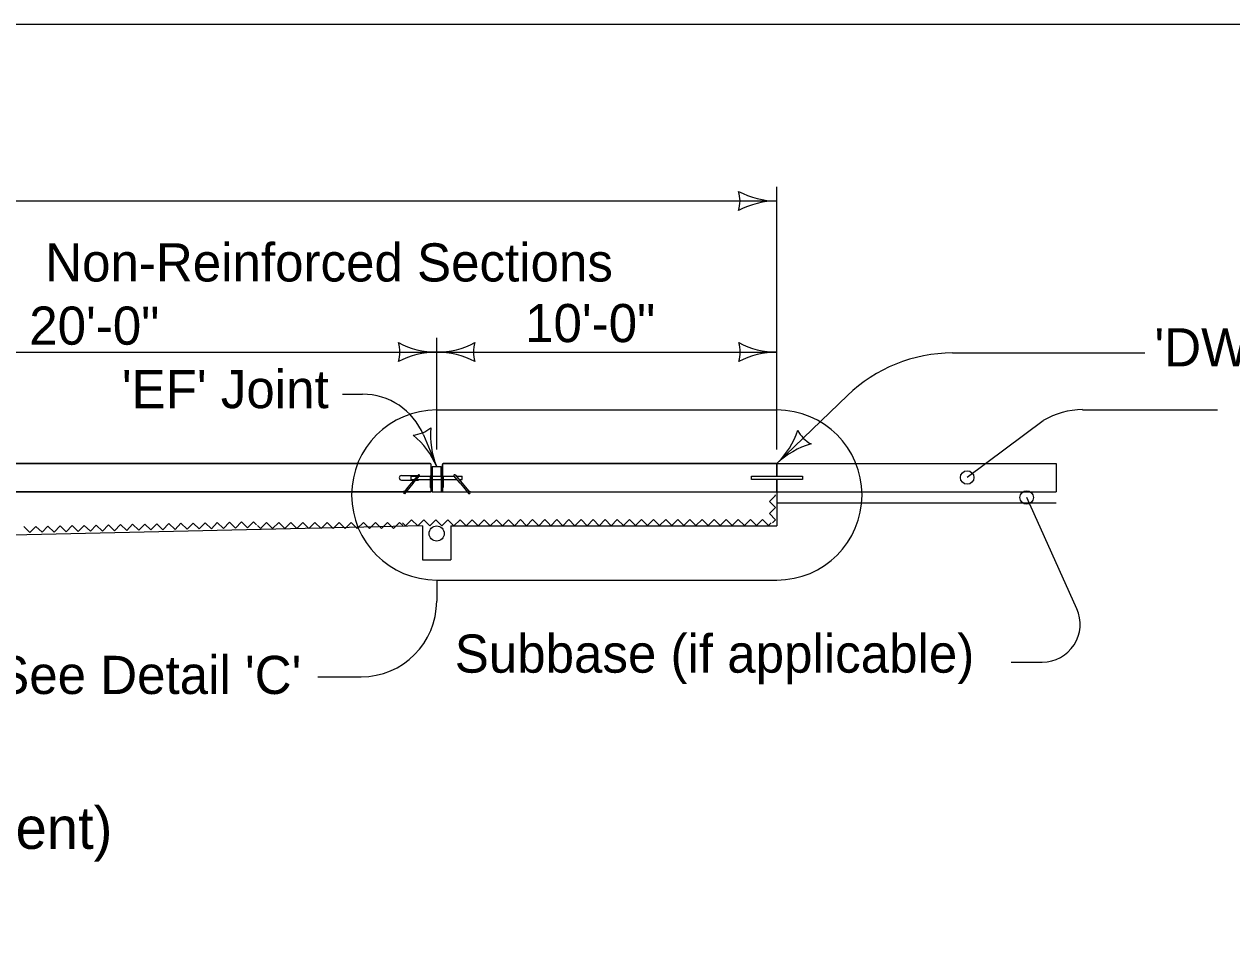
# Model space of a CAD drawing. Extents: x 10130 to 81668, y 5440 to 21644.
# Drawn here: x 15102 to 15735, y 7067 to 7554 of the extents above; entities that cross this region are included whole.
import ezdxf

# ---------------------------------------------------------------- set-up
doc = ezdxf.new("R2010")
doc.units = 0
for name, color, linetype in [('Cell', 7, 'Continuous'), ('dsnCellElements', 7, 'Continuous'), ('dsnStdBlockModified', 7, 'Continuous'), ('dsnStdBlockNotModified', 7, 'Continuous'), ('dsnStdBorder', 7, 'Continuous')]:
    doc.layers.add(name, color=color, linetype=linetype)

msp = doc.modelspace()

# ---------------------------------------------------------------- linework, layer by layer
at = {"layer": 'Cell'}
msp.add_lwpolyline([(13803.17, 7554.12), (16938.17, 7554.12), (16938.17, 5544.12), (13803.17, 5544.12)], close=True, dxfattribs=at)
at = {"layer": 'dsnCellElements'}
for centre in [(15596.22, 7316.59), (15627.37, 7306.09)]:
    msp.add_circle(centre, 3.54, dxfattribs=at)
at = {"layer": 'dsnStdBlockModified'}
for p, q in [((15496.58, 7331.28), (15496.58, 7468.91)), ((14157.11, 7461.48), (15496.58, 7461.48)), ((15318.38, 7331.28), (15318.38, 7389.71)), ((14961.98, 7382.28), (15318.38, 7382.28)), ((15318.38, 7382.28), (15496.58, 7382.28)), ((15588.54, 7381.82), (15689.23, 7381.82)), ((15269.11, 7360.25), (15279.46, 7360.25)), ((15496.58, 7323.85), (15533.47, 7359.54)), ((15318.38, 7351.95), (15496.58, 7351.95)), ((15656.65, 7352.11), (15727.26, 7352.11)), ((15636.08, 7346.35), (15596.22, 7316.59)), ((15653.61, 7247.79), (15627.37, 7306.09)), ((15318.38, 7262.85), (15318.38, 7251.75)), ((15318.38, 7262.85), (15496.58, 7262.85)), ((15619.33, 7219.86), (15635.56, 7219.86)), ((15256.14, 7212.15), (15278.78, 7212.15))]:
    msp.add_line(p, q, dxfattribs=at)
for centre, radius, start, end in [((15588.54, 7302.62), 79.2, 90, 134.04978), ((15279.46, 7325.6), 34.65, 22.59071, 90), ((15318.38, 7307.4), 44.55, 90, 270), ((15496.58, 7307.4), 44.55, 270, 90), ((15656.65, 7312.52), 39.6, 90, 121.29536), ((15278.78, 7251.75), 39.6, 270, 360), ((15635.56, 7239.67), 19.8, 270, 24.23803)]:
    msp.add_arc(centre, radius, start, end, dxfattribs=at)
at = {"layer": 'dsnStdBlockNotModified'}
for centre, radius, start, end in [((15282.75, 7382.28), 16.42, 342.26665, 17.73335), ((15318.38, 7424.78), 42.5, 241.92751, 270), ((15318.38, 7339.78), 42.5, 90, 118.07249), ((15318.38, 7424.78), 42.5, 270, 298.07249), ((15318.38, 7339.78), 42.5, 61.92751, 90), ((15354.02, 7382.28), 16.42, 162.26665, 197.73335), ((15460.95, 7382.28), 16.42, 342.26665, 17.73335), ((15496.58, 7424.78), 42.5, 241.92751, 270), ((15496.58, 7339.78), 42.5, 90, 118.07249), ((15304.69, 7355.15), 16.42, 274.86526, 310.33197), ((15279.15, 7305.92), 42.5, 22.59862, 50.6711), ((15357.62, 7338.58), 42.5, 174.52613, 202.59862), ((15467.03, 7354.4), 42.5, 314.0496, 342.12209), ((15522.2, 7348.63), 16.42, 206.31625, 241.78295), ((15526.13, 7293.31), 42.5, 105.97712, 134.0496)]:
    msp.add_arc(centre, radius, start, end, dxfattribs=at)
at = {"layer": 'dsnStdBorder'}
for p, q in [((15311.45, 7338.91), (15318.38, 7322.25)), ((14160.08, 7323.85), (15314.99, 7323.85)), ((15315, 7323.86), (14961.98, 7323.86)), ((15308.78, 7317.91), (15305.09, 7313.52)), ((15315.41, 7317.34), (15315.41, 7323.44)), ((15315.41, 7313.52), (15315.41, 7323.44)), ((15315.41, 7322.25), (15316.01, 7322.25)), ((15315.47, 7322.25), (15315.47, 7313.52)), ((15315.53, 7322.25), (15315.53, 7313.52)), ((15315.59, 7322.25), (15315.59, 7313.52)), ((15315.65, 7322.25), (15315.65, 7313.52)), ((15315.71, 7322.25), (15315.71, 7313.52)), ((15315.77, 7322.25), (15315.77, 7313.52)), ((15315.82, 7322.25), (15315.82, 7313.52)), ((15315.89, 7322.25), (15315.89, 7313.52)), ((15315.94, 7322.25), (15315.94, 7313.52)), ((15320.76, 7322.25), (15316.01, 7322.25)), ((15316.01, 7322.25), (15316.01, 7317.32)), ((15320.76, 7317.32), (15320.76, 7322.25)), ((15320.76, 7322.25), (15321.35, 7322.25)), ((15320.81, 7322.25), (15320.81, 7313.52)), ((15320.88, 7322.25), (15320.88, 7313.52)), ((15320.93, 7322.25), (15320.93, 7313.52)), ((15321, 7322.25), (15321, 7313.52)), ((15321.05, 7322.25), (15321.05, 7313.52)), ((15321.11, 7322.25), (15321.11, 7313.52)), ((15321.17, 7322.25), (15321.17, 7313.52)), ((15321.23, 7322.25), (15321.23, 7313.52)), ((15321.29, 7322.25), (15321.29, 7313.52)), ((15321.35, 7323.44), (15321.35, 7317.32)), ((15321.35, 7313.52), (15321.35, 7323.44)), ((15321.76, 7323.85), (15496.58, 7323.85)), ((15496.58, 7323.86), (15321.77, 7323.86)), ((15327.99, 7317.91), (15331.67, 7313.52)), ((15496.58, 7317.36), (15496.58, 7323.86)), ((15496.58, 7323.85), (15496.58, 7317.36)), ((15496.58, 7323.85), (15642.76, 7323.85)), ((15642.76, 7323.85), (15642.76, 7309)), ((15299.97, 7317.62), (15308.53, 7317.62)), ((15299.97, 7315.24), (15306.54, 7315.24)), ((15305.09, 7313.52), (15303.34, 7311.43)), ((15306.02, 7313.52), (15304.27, 7311.43)), ((15305.01, 7315.54), (15305.01, 7317.32)), ((15305.01, 7317.32), (15308.28, 7317.32)), ((15305.01, 7315.54), (15306.79, 7315.54)), ((15306.02, 7313.52), (15309.32, 7317.45)), ((15307.47, 7315.24), (15308.88, 7315.24)), ((15307.72, 7315.54), (15315.06, 7315.54)), ((15308.88, 7315.54), (15308.88, 7315.24)), ((15309.21, 7317.32), (15315.06, 7317.32)), ((15315.06, 7311.38), (15315.06, 7317.32)), ((15315.06, 7311.38), (15315.06, 7317.32)), ((15315.23, 7317.5), (15315.23, 7317.5)), ((15315.41, 7311.43), (15315.41, 7313.52)), ((15315.47, 7313.52), (15315.47, 7311.43)), ((15315.53, 7313.52), (15315.53, 7311.43)), ((15315.59, 7313.52), (15315.59, 7311.43)), ((15315.65, 7313.52), (15315.65, 7311.43)), ((15315.71, 7313.52), (15315.71, 7311.43)), ((15315.77, 7313.52), (15315.77, 7311.43)), ((15315.82, 7313.52), (15315.82, 7311.43)), ((15315.89, 7313.52), (15315.89, 7311.43)), ((15315.94, 7313.52), (15315.94, 7311.43)), ((15316.01, 7317.32), (15316.01, 7315.54)), ((15316.01, 7317.32), (15320.76, 7317.32)), ((15316.01, 7315.54), (15320.76, 7315.54)), ((15316.01, 7315.54), (15316.01, 7313.52)), ((15316.01, 7313.52), (15316.01, 7311.43)), ((15320.76, 7317.32), (15320.76, 7315.54)), ((15320.76, 7315.54), (15320.76, 7313.52)), ((15320.76, 7313.52), (15320.76, 7311.43)), ((15320.81, 7313.52), (15320.81, 7311.43)), ((15320.88, 7313.52), (15320.88, 7311.43)), ((15320.93, 7313.52), (15320.93, 7311.43)), ((15321, 7313.52), (15321, 7311.43)), ((15321.05, 7313.52), (15321.05, 7311.43)), ((15321.11, 7313.52), (15321.11, 7311.43)), ((15321.17, 7313.52), (15321.17, 7311.43)), ((15321.23, 7313.52), (15321.23, 7311.43)), ((15321.29, 7313.52), (15321.29, 7311.43)), ((15321.35, 7311.43), (15321.35, 7313.52)), ((15321.71, 7317.32), (15321.71, 7311.38)), ((15321.71, 7311.38), (15321.71, 7317.32)), ((15321.71, 7317.32), (15327.55, 7317.32)), ((15321.71, 7315.54), (15329.04, 7315.54)), ((15330.74, 7313.52), (15327.44, 7317.45)), ((15328.48, 7317.32), (15331.74, 7317.32)), ((15329.97, 7315.54), (15331.74, 7315.54)), ((15330.74, 7313.52), (15332.49, 7311.43)), ((15331.67, 7313.52), (15333.42, 7311.43)), ((15331.74, 7315.54), (15331.74, 7317.32)), ((15483.21, 7315.5), (15483.21, 7317.36)), ((15483.21, 7317.36), (15496.58, 7317.36)), ((15483.21, 7315.5), (15483.21, 7317.36)), ((15483.21, 7317.36), (15509.94, 7317.36)), ((15496.58, 7315.5), (15483.21, 7315.5)), ((15509.94, 7315.5), (15483.21, 7315.5)), ((15496.58, 7309.01), (15496.58, 7315.5)), ((15496.58, 7315.5), (15496.58, 7309)), ((15509.94, 7317.36), (15509.94, 7315.5)), ((15301.31, 7309), (14160.08, 7309)), ((14961.98, 7309.01), (15301.31, 7309.01)), ((15303.34, 7311.43), (15300.93, 7308.55)), ((15301.47, 7308.09), (15300.93, 7308.55)), ((15301.31, 7309.01), (15315.41, 7309.01)), ((15315.41, 7309), (15301.31, 7309.01)), ((15304.27, 7311.43), (15301.47, 7308.09)), ((15315.41, 7309), (15315.41, 7311.43)), ((15315.41, 7309.01), (15315.41, 7311.38)), ((15315.47, 7311.43), (15315.47, 7309)), ((15315.53, 7311.43), (15315.53, 7309)), ((15315.59, 7311.43), (15315.59, 7309)), ((15315.65, 7311.43), (15315.65, 7309)), ((15315.71, 7311.43), (15315.71, 7309)), ((15315.77, 7311.43), (15315.77, 7309)), ((15315.82, 7311.43), (15315.82, 7309)), ((15315.89, 7311.43), (15315.89, 7309)), ((15315.94, 7311.43), (15315.94, 7309)), ((15316.01, 7311.43), (15316.01, 7309)), ((15316.01, 7309), (15320.76, 7309)), ((15320.76, 7311.43), (15320.76, 7309)), ((15320.76, 7309), (15496.58, 7309)), ((15320.81, 7311.43), (15320.81, 7309)), ((15320.88, 7311.43), (15320.88, 7309)), ((15320.93, 7311.43), (15320.93, 7309)), ((15321, 7311.43), (15321, 7309)), ((15321.05, 7311.43), (15321.05, 7309)), ((15321.11, 7311.43), (15321.11, 7309)), ((15321.17, 7311.43), (15321.17, 7309)), ((15321.23, 7311.43), (15321.23, 7309)), ((15321.29, 7311.43), (15321.29, 7309)), ((15321.35, 7309), (15321.35, 7311.43)), ((15321.35, 7311.38), (15321.35, 7309.01)), ((15321.35, 7309.01), (15496.58, 7309.01)), ((15332.49, 7311.43), (15335.29, 7308.09)), ((15333.42, 7311.43), (15335.84, 7308.55)), ((15335.29, 7308.09), (15335.84, 7308.55)), ((15496.58, 7309), (15496.58, 7291.18)), ((15496.58, 7309), (15642.76, 7309)), ((15642.76, 7303.06), (15496.58, 7303.06)), ((15310.95, 7291.18), (14193.72, 7265.94)), ((15310.95, 7291.18), (15310.95, 7273.36)), ((15325.8, 7291.18), (15496.58, 7291.18)), ((15325.8, 7291.18), (15325.8, 7273.36)), ((15310.95, 7273.36), (15325.8, 7273.36))]:
    msp.add_line(p, q, dxfattribs=at)
for points in [[(15321.35, 7317.32), (15321.35, 7317.32)], [(15494.27, 7292.9), (15495.85, 7294.48), (15492.68, 7297.65), (15495.85, 7300.82), (15492.68, 7303.98), (15495.85, 7307.15), (15495.42, 7307.58)], [(15148.08, 7290.23), (15149.69, 7288.68), (15152.8, 7291.91), (15156.03, 7288.81), (15159.13, 7292.05), (15162.37, 7288.95), (15165.46, 7292.18), (15168.7, 7289.09), (15171.8, 7292.32), (15175.03, 7289.22), (15178.13, 7292.46), (15181.37, 7289.35), (15184.47, 7292.59), (15187.7, 7289.49), (15190.8, 7292.73), (15194.04, 7289.62), (15197.14, 7292.86), (15200.37, 7289.76), (15203.47, 7293), (15206.71, 7289.9), (15209.81, 7293.13), (15213.04, 7290.03), (15216.14, 7293.27), (15219.37, 7290.17), (15222.48, 7293.4), (15224.09, 7291.85)], [(15224.55, 7291.39), (15226.13, 7289.81), (15229.3, 7292.97), (15232.47, 7289.81), (15235.63, 7292.99), (15238.81, 7289.82), (15241.97, 7292.99), (15245.14, 7289.83), (15248.31, 7293), (15251.48, 7289.84), (15254.64, 7293.01), (15257.81, 7289.85), (15260.98, 7293.02), (15264.15, 7289.85), (15267.31, 7293.03), (15270.49, 7289.86), (15273.65, 7293.03), (15276.82, 7289.87), (15279.99, 7293.04), (15283.16, 7289.88), (15286.32, 7293.05), (15289.49, 7289.89), (15292.66, 7293.06), (15295.83, 7289.89), (15298.99, 7293.07), (15300.58, 7291.49)], [(15300.52, 7292.88), (15302.11, 7291.3), (15305.27, 7294.46), (15308.44, 7291.3), (15311.61, 7294.46), (15314.78, 7291.3), (15317.95, 7294.47), (15321.11, 7291.3), (15324.28, 7294.47), (15327.45, 7291.3), (15330.62, 7294.47), (15333.79, 7291.3), (15336.95, 7294.48), (15340.12, 7291.31), (15343.29, 7294.48), (15346.46, 7291.31), (15349.63, 7294.48), (15352.79, 7291.31), (15355.96, 7294.48), (15359.13, 7291.32), (15362.3, 7294.49), (15365.47, 7291.32), (15368.63, 7294.49), (15371.8, 7291.32), (15374.97, 7294.49), (15376.55, 7292.91)], [(15376.55, 7292.91), (15378.14, 7291.32), (15381.31, 7294.5), (15384.47, 7291.33), (15387.64, 7294.5), (15390.81, 7291.33), (15393.98, 7294.5), (15397.15, 7291.33), (15400.31, 7294.5), (15403.48, 7291.33), (15406.65, 7294.5), (15409.82, 7291.33), (15412.99, 7294.5), (15416.15, 7291.34), (15419.32, 7294.51), (15422.49, 7291.34), (15425.66, 7294.51), (15428.83, 7291.34), (15431.99, 7294.51), (15435.16, 7291.34), (15438.33, 7294.52), (15441.5, 7291.35), (15444.67, 7294.52), (15447.83, 7291.35), (15451, 7294.52), (15452.59, 7292.93)], [(15452.59, 7292.93), (15454.17, 7291.35), (15457.34, 7294.52), (15460.51, 7291.35), (15463.67, 7294.53), (15466.84, 7291.36), (15470.01, 7294.53), (15473.18, 7291.36), (15476.35, 7294.53), (15479.51, 7291.36), (15482.68, 7294.53), (15485.85, 7291.37), (15489.02, 7294.53), (15492.19, 7291.37), (15493.56, 7292.74)], [(15102.12, 7290.83), (15105.35, 7287.73), (15108.46, 7290.96), (15111.69, 7287.87), (15114.79, 7291.1), (15118.02, 7288), (15121.12, 7291.24), (15124.36, 7288.14), (15127.46, 7291.37), (15130.69, 7288.27), (15133.79, 7291.51), (15137.03, 7288.4), (15140.13, 7291.64), (15143.36, 7288.54), (15146.46, 7291.78), (15148.08, 7290.23)]]:
    msp.add_lwpolyline(points, dxfattribs=at)
for centre, radius in [((15306.03, 7315), 0.238), ((15330.49, 7315.3), 0.238), ((15301.2, 7309.24), 0.238), ((15335.57, 7309.24), 0.238), ((15318.38, 7287.22), 3.96)]:
    msp.add_circle(centre, radius, dxfattribs=at)
for centre, radius, start, end in [((15460.74, 7461.48), 16.51, 342.26665, 17.73335), ((15496.58, 7504.23), 42.75, 241.92751, 270), ((15460.74, 7461.48), 16.51, 342.26665, 17.73335), ((15496.58, 7504.23), 42.75, 241.92751, 270), ((15496.58, 7418.73), 42.75, 90, 118.07249), ((15496.58, 7418.73), 42.75, 90, 118.07249), ((15309.05, 7317.68), 0.356, 320.00367, 139.99636), ((15315, 7323.44), 0.416, 360, 90), ((15315, 7323.44), 0.416, 0, 90), ((15321.77, 7323.44), 0.416, 90, 180), ((15321.77, 7323.44), 0.416, 90, 180), ((15327.72, 7317.68), 0.356, 40.00364, 219.99633), ((15299.97, 7316.43), 1.19, 90, 270), ((15315.23, 7317.32), 0.178, 5.43269, 180), ((15315.24, 7317.32), 0.178, 0, 180), ((15315.24, 7317.32), 0.178, 0, 180), ((15321.53, 7317.32), 0.178, 0, 180), ((15321.53, 7317.32), 0.178, 0, 180), ((15315.23, 7311.38), 0.178, 180, 359.93724), ((15315.24, 7311.38), 0.178, 180, 0), ((15321.53, 7311.38), 0.178, 180, 0), ((15321.53, 7311.38), 0.178, 180, 0)]:
    msp.add_arc(centre, radius, start, end, dxfattribs=at)
for points in [[(15321.71, 7317.2), (15321.74, 7317.2), (15321.77, 7317.2), (15321.8, 7317.2), (15321.82, 7317.2), (15321.84, 7317.2), (15321.85, 7317.2)], [(15321.71, 7317.08), (15321.74, 7317.08), (15321.77, 7317.08), (15321.8, 7317.08), (15321.82, 7317.08), (15321.84, 7317.08), (15321.85, 7317.08)], [(15321.71, 7316.96), (15321.74, 7316.96), (15321.77, 7316.96), (15321.8, 7316.96), (15321.82, 7316.96), (15321.84, 7316.96), (15321.85, 7316.96)], [(15321.71, 7316.85), (15321.74, 7316.84), (15321.77, 7316.85), (15321.8, 7316.85), (15321.82, 7316.85), (15321.84, 7316.84), (15321.85, 7316.85)], [(15321.71, 7316.73), (15321.74, 7316.72), (15321.77, 7316.73), (15321.8, 7316.73), (15321.82, 7316.73), (15321.84, 7316.72), (15321.85, 7316.73)], [(15321.71, 7316.61), (15321.74, 7316.6), (15321.77, 7316.61), (15321.8, 7316.61), (15321.82, 7316.61), (15321.84, 7316.6), (15321.85, 7316.61)], [(15321.71, 7316.49), (15321.74, 7316.48), (15321.77, 7316.49), (15321.8, 7316.49), (15321.82, 7316.49), (15321.84, 7316.48), (15321.85, 7316.49)], [(15321.71, 7316.37), (15321.74, 7316.37), (15321.77, 7316.37), (15321.8, 7316.37), (15321.82, 7316.37), (15321.84, 7316.37), (15321.85, 7316.37)], [(15321.71, 7316.25), (15321.74, 7316.25), (15321.77, 7316.25), (15321.8, 7316.25), (15321.82, 7316.25), (15321.84, 7316.25), (15321.85, 7316.25)], [(15321.71, 7316.13), (15321.74, 7316.13), (15321.77, 7316.13), (15321.8, 7316.13), (15321.82, 7316.13), (15321.84, 7316.13), (15321.85, 7316.13)], [(15321.71, 7316.01), (15321.74, 7316.01), (15321.77, 7316.01), (15321.8, 7316.01), (15321.82, 7316.01), (15321.84, 7316.01), (15321.85, 7316.01)], [(15321.71, 7315.89), (15321.74, 7315.89), (15321.77, 7315.89), (15321.8, 7315.89), (15321.82, 7315.89), (15321.84, 7315.89), (15321.85, 7315.89)], [(15321.71, 7315.78), (15321.74, 7315.77), (15321.77, 7315.78), (15321.8, 7315.78), (15321.82, 7315.78), (15321.84, 7315.77), (15321.85, 7315.78)], [(15321.71, 7315.66), (15321.74, 7315.65), (15321.77, 7315.66), (15321.8, 7315.66), (15321.82, 7315.66), (15321.84, 7315.65), (15321.85, 7315.66)]]:
    msp.add_spline(points, degree=3, dxfattribs=at)

# ---------------------------------------------------------------- texts
at = {"layer": 'dsnStdBlockModified'}
for s, height, p in [('Non-Reinforced Sections', 20, (15113.36, 7419.28)), ('20\'-0"', 20, (15105.01, 7386.16)), ('10\'-0"', 20, (15364.7, 7387.49)), ("'DW' or 'RT' Joint", 20, (15694.29, 7374.79)), ("'EF' Joint", 20, (15153.51, 7352.9)), ('Subbase (if applicable)', 20, (15327.85, 7214.31)), ("See Detail 'C'", 20, (15087.16, 7203.14)), ('(Abutting PCC or Composite Pavement)', 22, (14626.96, 7121.97))]:
    msp.add_text(s, height=height, dxfattribs=at).set_placement(p)

doc.saveas('drawing.dxf')
